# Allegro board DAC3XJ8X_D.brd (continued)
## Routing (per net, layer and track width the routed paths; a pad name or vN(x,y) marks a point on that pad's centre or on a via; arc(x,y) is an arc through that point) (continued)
ALARM: length 15.5
  BOTTOM w0.102: TP24.1 129.41,90.55 126.64,93.32 123.52,93.32 123.11,92.91 119.27,92.91 118.79,92.43 117.98,92.43 117.79,92.63 v2(116.42,92.63)
AMUX0: length 40.3
  TOP w0.152: TP2.1 133.1,74.17 v1(133.1,84.2)
  BOTTOM w0.102: v1(133.1,84.2) 134.34,84.2 135.38,85.24 135.38,86.46 134.52,87.33 133.3,87.33 132.44,86.46 132.44,85.95 130.81,84.33 128.14,84.33 126.82,85.66 125.86,85.66 124.94,84.73 118.04,84.73 118.04,84.74 117.96,84.74 117.58,85.12 117.58,85.2 116.24,86.54 115.9,86.54 115.19,87.25 114.86,87.25 114.44,87.67 114.44,87.95 114.15,88.24 114.15,88.5 v2(114.02,88.63)
AMUX1: length 27.7
  TOP w0.102: v1(125.98,84.96) 125.98,78.87 TP1.1
  BOTTOM w0.102: v1(125.98,84.96) 125.53,84.51 115.82,84.51 115.44,84.12 112.47,84.12 112.01,84.58 112.01,88.27 111.65,88.63 v2(111.62,88.63)
AN_OUT: length 2.4
  TOP w0.483: R14.1 T2.4
ANOUT: length 8.4
  TOP w0.483: J4.1 64.02,138.85 69.46,133.41 69.46,133.02 R14.2
AP_OUT: length 2.2
  TOP w0.483: T2.6 R15.2
APOUT: length 8.7
  TOP w0.483: J2.1 60.09,124.1 60.54,124.1 R2.1
ATEST: length 14.5
  TOP w0.102: v1(119.38,93.6) 118.88,93.6 118.6,93.32 117.65,93.32 117.38,93.05 116.26,93.05 115.88,93.43 U2.K9
  BOTTOM w0.102: v1(119.38,93.6) 119.66,93.88 129.01,93.88 TP23.1
BN_OUT: length 2.2
  TOP w0.483: T4.6 R27.1
BNOUT: length 8.7
  TOP w0.483: J8.1 92.07,142.08 92.39,141.76 R27.2
BP_OUT: length 2.4
  TOP w0.483: R19.2 T4.4
BPOUT: length 8.4
  TOP w0.483: R17.2 105,141.76 105.28,142.04 J6.1
CAR_SYSREFM: length 124.9
  TOP w0.229: v1(115.09,54.2) 115.09,53.78 114.65,53.34 107,53.34 106.21,54.13 106.21,64.23 105.41,65.02 102.77,65.02 100.61,67.18 93.98,67.18 R108.2
  BOTTOM w0.229: J16.G10 159.38,15.75 159.38,7.78 159.13,7.52 140.69,7.52 140.33,7.87 140.33,22 134.42,27.91 134.42,32.54 134.87,32.99 134.87,33.99 134.42,34.45 134.42,34.88 134.87,35.34 134.87,36.04 134.42,36.5 134.42,37.01 133.97,37.46 133.46,37.46 133.24,37.69 133.24,38.07 133.46,38.3 133.97,38.3 134.42,38.75 134.42,40.34 119.89,54.86 115.75,54.86 v1(115.09,54.2)
CAR_SYSREFP: length 124.9
  TOP w0.229: v1(115.78,53.51) 115.36,53.51 114.81,52.96 106.84,52.96 105.83,53.98 105.83,64.07 105.25,64.64 102.62,64.64 100.46,66.8 93.98,66.8 R109.2
  BOTTOM w0.229: v1(115.78,53.51) 116.76,54.48 119.73,54.48 134.04,40.18 134.04,38.91 133.81,38.68 133.31,38.68 132.85,38.22 132.85,37.53 133.31,37.08 133.81,37.08 134.04,36.85 134.04,27.76 139.06,22.73 139.06,8.61 140.53,7.14 159.28,7.14 160.66,8.51 160.66,15.75 J16.G9
CLK_IN: length 5.8
  TOP w0.483: C122.1 v1(82.42,49.78)
  BOTTOM w0.483: R177.2 v1(82.42,49.78)
CLK_LAO_0M: length 124.9
  BOTTOM w0.229: J16.G7 164.47,15.75 164.47,7.45 163.27,6.25 135.03,6.25 133.98,7.29 133.98,21.09 130.33,24.75 130.33,40.29 120.25,50.37 119.2,50.37 118.77,50.8 117.57,50.8 117.13,50.37 116.65,50.37 116.3,50.72 115.81,50.72 115.46,50.37 114.98,50.37 114.62,50.72 114.14,50.72 113.78,50.37 113.04,50.37 112.81,50.6 112.81,51.29 112.36,51.74 111.66,51.74 111.21,51.29 111.21,50.6 110.98,50.37 110.6,50.37 110.37,50.6 110.37,51.24 109.92,51.69 109.22,51.69 108.77,51.24 108.77,50.6 108.54,50.37 107.65,50.37 106.17,51.85 106.17,57.35 104.85,58.67 96.65,58.67 v1(96.27,59.06)
CLK_LAO_0P: length 124.9
  BOTTOM w0.229: v1(96.27,57.91) 96.65,58.29 104.69,58.29 105.79,57.2 105.79,51.69 107.49,49.99 108.7,49.99 109.15,50.44 109.15,51.08 109.38,51.31 109.76,51.31 109.99,51.08 109.99,50.44 110.44,49.99 111.14,49.99 111.59,50.44 111.59,51.13 111.82,51.36 112.2,51.36 112.43,51.13 112.43,50.44 112.88,49.99 120.09,49.99 129.95,40.13 129.95,24.59 132.72,21.82 132.72,8.02 134.87,5.87 163.42,5.87 165.68,8.13 165.68,15.8 J16.G6
CLKIN: length 5.1
  BOTTOM w0.483: R177.1 J17.1
CLKIN1N: length 3.9
  TOP w0.229: U5.35 83.35,53.6 83.29,53.54 83.29,52.34 C78.2 C198.2
CLKIN1P: length 2.8
  TOP w0.229: C122.2 82.91,52.43 82.91,53.54 82.85,53.6 U5.34
CLKLA_0N: length 8.8
  TOP w0.229: U5.63 91.56,62.31 91.62,62.25 92.6,62.25 93.34,61.5 93.34,59.09 93.76,58.67 94.87,58.67 C89.2 R80.1
CLKLA_0P: length 8.8
  TOP w0.229: R79.1 C86.2 94.87,58.29 93.6,58.29 92.96,58.93 92.96,61.34 92.44,61.87 91.62,61.87 91.56,61.81 U5.62
CLKN: length 20.1
  TOP w0.229: 83.69,86.36 83.31,85.98 83.31,79.5 81.28,77.47 80.55,77.47 78.82,75.74 78.82,74.12 80.75,72.19 80.75,71.09 R182.1 81.18,70.66 81.18,69.75 C340.2
CLKOUT0_N: length 1.6
  TOP w0.483: J18.1 C83.2
CLKOUT0_P: length 1.6
  TOP w0.483: J13.1 C79.2
CLKOUT1_N: length 2
  TOP w0.483: J20.1 C93.2
CLKOUT1_P: length 2
  TOP w0.483: J19.1 C91.2
CLKP: length 20.1
  TOP w0.229: 82.55,86.36 82.93,85.98 82.93,79.66 81.12,77.85 80.39,77.85 78.44,75.9 78.44,73.96 80.37,72.03 80.37,71.17 R181.1 79.88,70.69 C341.2
CMOS_SYNC_AB: length 113.1
  TOP w0.152: v1(149.99,34.93) 149.99,22.23 149.22,21.46 149.22,15.14 148.77,14.68 147.75,14.68 v2(147.32,15.11) ; v1(122.55,90.81) 122.63,90.73 122.63,81.2 v1(122.33,80.9) ; J21.1 144.65,82.02 144.65,80.3 145.58,79.38 147.22,79.38 147.45,79.15 v1(147.45,59.31)
  BOTTOM w0.152: v1(147.45,59.31) 147.45,40.01 149.99,37.47 v1(149.99,34.93) ; v2(116.42,91.03) 116.59,91.2 118.08,91.2 118.18,91.3 119.79,91.3 119.85,91.24 121.23,91.24 121.62,90.86 122.1,90.86 122.15,90.81 v1(122.55,90.81) ; v1(122.33,80.9) 122.63,81.2 122.73,81.2 123.19,81.66 138.94,81.66 140.72,83.44 143.23,83.44 J21.1
CMOS_SYNC_CD: length 106.5
  TOP w0.152: v1(149.1,36.32) 149.1,23.88 148.08,22.86 148.08,15.62 v2(148.59,15.11) ; v1(123.31,80.9) 123.31,88.64 123.05,88.9 123.05,91.3 v1(123.06,91.31) ; J21.3 144.78,79.35 v1(144.78,59.31)
  BOTTOM w0.152: v1(123.31,80.9) 124.08,80.14 129.16,80.14 129.64,80.62 J21.3 ; v1(144.78,59.31) 144.78,40.64 v1(149.1,36.32) ; v1(123.06,91.31) 122.73,91.31 122.36,91.68 116.98,91.68 116.84,91.83 v2(116.42,91.83)
CN_OUT: length 2.4
  TOP w0.483: T6.4 R41.2
CNOUT: length 8.4
  TOP w0.483: R42.2 133.32,141.76 133.6,142.04 J10.1
CP1: length 56.5
  TOP w0.152: U5.32 81.53,54.72 81.58,54.66 81.58,54.3 81.53,54.25 81.53,53.58 81.58,53.52 81.58,53.16 81.53,53.1 81.53,52.7 v1(80.01,51.18) C61.1 ; C120.2 115.54,37.62 v1(114.93,38.23) 111.44,38.23 Y1.1
  BOTTOM w0.152: v1(80.01,51.18) 80.52,50.67 82.93,50.67 83.31,50.29 84.84,50.29 85.34,49.78 86.36,49.78 87.63,48.51 87.63,40.01 88.77,38.86 114.3,38.86 v1(114.93,38.23)
CP2: length 3.7
  TOP w0.152: U5.46 88.86,52.11 C63.1 C62.1
CP_OUT: length 2.2
  TOP w0.483: T6.6 R102.2
CPLD_SYNC: length 67
  TOP w0.305: U1.82 v1(45.95,81.25)
  BOTTOM w0.483: SJP2.3 97.28,66.33 97.18,66.42 93.22,66.42 92.57,65.77 92.2,65.4 92.07,65.28 91.71,64.91 88.48,64.91 88.12,65.28 87.99,65.41 87.88,65.41 86.61,66.68 78.51,66.68 78.14,67.04 62.25,67.04 60.45,68.83 60.45,78.23 58.8,79.88 46.58,79.88 45.95,80.52 v1(45.95,81.25)
CPOUT: length 8.7
  TOP w0.483: J9.1 120.4,142.08 120.71,141.76 R30.2
DAC_RESET: length 134.4
  TOP w0.102: U1.37 49.45,99.73 49.28,99.9 v1(49.28,103.25)
  TOP w0.152: R63.2 SW1.3 SW1.4 C168.1
  BOTTOM w0.102: v1(142.24,90.04) 138.43,90.04 137.34,91.14 132.59,91.14 131.7,90.25 131.7,88.39 131.47,88.16 128.5,88.16 127.76,88.9 127.76,91.74 126.42,93.09 123.85,93.09 123.44,92.68 119.37,92.68 118.88,92.2 116.59,92.2 116.58,92.21 116.26,92.21 116.26,92.2 115.95,92.2 115.62,92.53 v2(115.62,92.63) 116.03,93.04 116.66,93.04 117.22,93.6 117.22,94.23 117.73,94.73 117.73,96.65 119.13,98.04 119.13,104.67 117.63,106.17 97.54,106.17 96.39,105.03 52.7,105.03 50.93,103.25 v1(49.28,103.25)
DAC_SCLK: length 86.1
  TOP w0.102: U1.33 51.45,102.96 v1(52.04,103.56)
  BOTTOM w0.102: v2(116.42,93.43) 116.81,93.82 116.81,96.37 118.87,98.43 118.87,104.27 117.22,105.92 97.79,105.92 96.65,104.78 76.66,104.78
  BOTTOM w0.152: 76.66,104.78 53.26,104.78 v1(52.04,103.56)
DAC_SDENB: length 96.6
  TOP w0.102: U2.M9 117.52,93.73 v1(117.98,93.73)
  TOP w0.152: v1(50.95,104.32) U1.34
  BOTTOM w0.102: 54.1,105.28 96.16,105.28 97.31,106.43 117.98,106.43 119.38,105.03 119.38,97.66 118.57,96.85 118.57,95.71 118.82,95.45 119.94,95.45 120.07,95.58 122.2,95.58 122.61,95.18 122.61,94.82 122.05,94.26 118.93,94.26 118.4,93.73 v1(117.98,93.73)
  BOTTOM w0.152: v1(50.95,104.32) 51.36,104.32 52.45,105.41 53.98,105.41 54.1,105.28
DAC_SDIO: length 99
  TOP w0.102: v1(118.24,95.25) 118.24,94.84 118.01,94.62 116.84,94.62 116.45,94.23 U2.L10 ; v1(121.41,95.12) v1(122.43,98.55)
  TOP w0.152: U1.35 v1(50.45,107.06)
  BOTTOM w0.102: v1(121.41,95.12) 118.36,95.12 v1(118.24,95.25) ; v1(122.43,98.55) 121.67,98.55 120.9,99.31 120.9,106.43 119.38,107.95 96.11,107.95 94.97,106.81 55.75,106.81 55.37,107.19 50.57,107.19 v1(50.45,107.06)
DAC_SDO: length 102.9
  TOP w0.102: v2(122.17,95) 122.18,95 v1(122.68,97.66) ; v2(118.36,94.23) 117.92,94.23 117.9,94.21 117.56,94.21 117.54,94.23 U2.M10
  TOP w0.152: U1.36 v1(49.95,107.57)
  BOTTOM w0.102: v1(122.68,97.66) 123.57,97.66 123.82,97.92 123.82,99.31 122.3,100.84 121.16,100.84 121.16,106.68 119.63,108.2 95.91,108.2 94.77,107.06 87.05,107.06 86.08,108.03 83.16,108.03 82.5,107.37 81.36,107.37 80.99,107.73 79.79,107.73 79.12,107.06 56.01,107.06 55.5,107.57 v1(49.95,107.57) ; v2(122.17,95) 121.77,94.59 118.73,94.59 v2(118.36,94.23)
DAC_TCLK: length 100.1
  TOP w0.102: v2(119.38,96.77) 120.32,95.83 120.32,92.23 119.53,91.44 117.02,91.44 116.81,91.24 116.81,90.02 116.64,89.84 116.03,89.84 U2.K4
  TOP w0.152: U1.40 v1(47.95,104.68)
  BOTTOM w0.102: 54.23,105.79 54.48,105.54 96.01,105.54 97.15,106.68 118.24,106.68 119.61,105.31 119.61,97 v2(119.38,96.77)
  BOTTOM w0.152: 54.23,105.79 52.02,105.79 51.64,105.41 48.64,105.41 47.95,104.72 v1(47.95,104.68)
DAC_TDI: length 100.2
  TOP w0.102: U2.L5 116.03,90.62 116.03,92.02 116.23,92.23 118.95,92.23 119.94,93.22 119.94,95.35 v1(119.38,95.91)
  TOP w0.152: U1.41 v1(47.45,105.16)
  BOTTOM w0.102: v1(47.45,105.16) 47.95,105.66 51.44,105.66 51.94,106.17 54.36,106.17 54.74,105.79 95.76,105.79 96.9,106.93 118.36,106.93 119.89,105.41 119.89,96.42 v1(119.38,95.91)
DAC_TDO: length 117
  TOP w0.102: v1(126.75,97.28) 127.38,96.65 127.38,89.53 127,89.15 v1(126.75,89.15) ; v2(121.92,89.51) 121.74,89.33 119.18,89.33 118.73,89.78 117.61,89.78 117.22,90.17 U2.M5
  TOP w0.152: U1.42 v1(46.95,105.61)
  BOTTOM w0.102: v1(46.95,105.61) 47.26,105.61 47.69,106.05 51.31,106.05 51.69,106.43 54.48,106.43 54.86,106.05 95.61,106.05 96.75,107.19 118.62,107.19 120.14,105.66 120.14,97.66 121.54,96.27 125.49,96.27 126.06,96.84 126.06,96.85 126.36,97.16 126.62,97.16 v1(126.75,97.28) ; v1(126.75,89.15) 126.44,89.15 126.16,89.43 125.84,89.43 125.79,89.48 125.41,89.48 125.36,89.43 122.28,89.43 122.23,89.48 122,89.48 121.97,89.51 v2(121.92,89.51)
DAC_TMS: length 116.9
  TOP w0.102: v1(125.6,97.03) 125.78,96.85 125.78,96.09 126.67,95.2 126.67,91.74 126.06,91.14 125.81,91.14 125.35,90.68 125.35,89.53 125.6,89.28 v1(125.6,89.03) ; v2(116.15,89.18) 116.4,89.43 U2.L4
  TOP w0.152: U1.43 v1(46.45,106.08)
  BOTTOM w0.102: v2(116.15,89.18) 116.33,89.01 116.58,89.01 116.66,88.93 120.14,88.93 120.22,88.85 120.58,88.85 120.65,88.93 125.37,88.93 125.48,89.03 v1(125.6,89.03) ; v1(125.6,97.03) 125.09,96.52 121.61,96.52 120.4,97.73 120.4,105.92 118.87,107.44 96.6,107.44 95.45,106.3 55.12,106.3 54.74,106.68 51.44,106.68 51.05,106.3 46.66,106.3 v1(46.45,106.08)
DAC_TRSTB: length 122.1
  TOP w0.102: v1(126.11,88.27) 126.11,88.9 126.31,89.1 126.31,89.33 126.57,89.59 126.8,89.59 127.13,89.92 127.13,91.42 127,91.55 127,95.76 126.11,96.65 v1(126.11,97.79) ; U2.J3 114.82,88.61 v2(114.58,88.37)
  TOP w0.152: v1(45.95,106.57) U1.44
  BOTTOM w0.102: v1(126.11,97.79) 125.72,97.79 124.7,96.77 121.69,96.77 120.65,97.82 120.65,106.17 119.13,107.7 96.27,107.7 95.12,106.55 55.5,106.55 55.12,106.93 51.05,106.93 50.69,106.57 v1(45.95,106.57) ; v2(114.58,88.37) 114.58,88.39 114.94,88.75 115.21,88.75 115.65,88.75 116.15,88.25 116.58,88.25 116.6,88.27 v1(126.11,88.27)
DCLK_N: length 30.2
  TOP w0.229: v1(105.54,92.96) 105.54,93.13 105.99,93.59 107.85,93.59 108,93.43 U2.A9
  BOTTOM w0.229: v1(83.69,87.38) 83.31,87.38 83.11,87.58 83.11,87.73 82.93,87.91 82.93,88.77 83.51,89.36 83.67,89.36 84.67,90.36 84.67,90.51 87.79,93.64 104.86,93.64 v1(105.54,92.96)
DCLK_P: length 30.2
  TOP w0.229: v1(105.54,94.62) 105.54,94.53 106.1,93.97 107.74,93.97 108,94.23 U2.A10
  BOTTOM w0.229: v1(105.54,94.62) 104.94,94.02 87.64,94.02 82.55,88.93 v1(82.55,87.38)
DCLKOUT0N: length 21.1
  TOP w0.229: U5.28 80.65,57.3 80.59,57.36 64.48,57.36 63.75,56.64 R76.1 C83.1
DCLKOUT0P: length 21.1
  TOP w0.229: C79.1 R75.1 63.75,58.47 64.48,57.74 80.59,57.74 80.65,57.8 U5.27
DCLKOUT2N: length 6.1
  TOP w0.229: C340.1 81.03,68.58 R179.1 81.03,67.17 80.77,66.91 80.77,66.45 82.85,64.37 U5.15
DCLKOUT2P: length 6.1
  TOP w0.229: U5.16 82.35,64.33 80.39,66.29 80.39,66.68 80.01,67.06 R180.1 80.01,68.58 C341.1
DCLKOUT8N: length 13
  TOP w0.229: R122.1 C74.1 97.66,53.09 96.99,53.09 96.48,53.59 95.53,53.59 95.03,53.09 94.65,53.09 94.23,53.5 94.23,56.77 93.66,57.34 92.65,57.34 92.05,56.74 91.62,56.74 91.56,56.8 U5.52
DCLKOUT8P: length 13
  TOP w0.229: U5.51 91.56,56.3 91.62,56.36 92.21,56.36 92.8,56.96 93.5,56.96 93.85,56.61 93.85,53.34 94.49,52.71 95.18,52.71 95.69,53.21 96.32,53.21 96.83,52.71 97.66,52.71 C75.1 R123.1
DN_OUT: length 2.2
  TOP w0.483: R103.2 158.92,130.37 T8.6
DNOUT: length 8.7
  TOP w0.483: R50.2 156.25,133.04 156.25,133.49 J11.1
DP0_C2M_N_A: length 100.5
  TOP w0.229: C190.1 120.6,88.01 121.13,88.01 121.23,87.91 121.23,82.5 120.03,81.3 120.03,79.04 120.01,79.02 120.01,78.71 147.9,50.82 147.9,50.39 148.28,50.02 148.7,50.02 149.66,49.06 149.66,48.51 150.15,48.02 150.7,48.02 151.18,47.54 151.18,46.99 151.67,46.5 152.22,46.5 164.08,34.64 164.08,16.69 164.92,15.85 165.73,15.85 166.73,14.86 167.64,14.86 168.28,14.22 168.66,14.22 169.04,13.84 169.04,11.43 v2(168.91,11.3)
DP0_C2M_P_A: length 100.5
  TOP w0.229: v2(170.18,11.3) 169.42,12.07 169.42,14 168.81,14.61 168.43,14.61 167.8,15.24 166.88,15.24 165.89,16.23 165.08,16.23 164.47,16.85 164.47,34.8 120.41,78.85 120.41,81.14 121.61,82.34 121.61,88.07 121.29,88.39 120.68,88.39 C191.1
DP1_C2M_N_A: length 93.5
  TOP w0.229: C193.1 117.22,83.57 116.97,83.31 116.97,79.28 122.59,73.66 122.59,73.63 135.76,60.45 135.76,25.68 141.1,20.35 141.1,19.23 141.33,19 141.33,18.49 141.1,18.26 141.1,14.64 144.3,11.43 145.06,11.43 146.94,9.56 146.94,8.26 146.05,7.37 144.72,7.37 144.27,7.82 144.27,8.38 143.89,8.76 v2(143.51,8.76)
DP1_C2M_P_A: length 93.5
  TOP w0.229: C192.1 116.46,83.57 116.59,83.44 116.59,79.12 122.21,73.5 122.21,73.47 135.38,60.29 135.38,39.19 134.87,38.68 134.87,38.3 135.38,37.79 135.38,37.41 134.87,36.9 134.87,36.52 135.38,36.01 135.38,35.63 134.87,35.12 134.87,34.74 135.38,34.23 135.38,32.71 135.05,32.38 135.05,30.94 135.38,30.61 135.38,25.53 136.38,24.53 136.38,24.25 136.86,23.76 137.15,23.76 137.35,23.56 137.35,23.28 137.83,22.79 138.12,22.79 138.32,22.59 138.32,22.31 138.8,21.82 139.09,21.82 140.72,20.19 140.72,14.48 144.14,11.05 144.91,11.05 146.56,9.4 146.56,8.41 145.89,7.75 144.88,7.75 144.72,7.91 144.72,8.7 v2(144.78,8.76)
DP2_C2M_N_A: length 86.7
  TOP w0.229: v1(138.43,8.76) 138.53,8.76 138.81,9.04 138.81,12.57 136.78,14.61 136.78,16.89 136.02,17.65 135.64,17.65 134.37,18.92 133.35,18.92 131.95,20.32 131.95,26.57 132.72,27.34 132.72,59.94 115.13,77.53 115.13,83.32 114.93,83.51 C195.1
DP2_C2M_P_A: length 86.7
  TOP w0.229: v1(139.7,8.76) 139.19,9.27 139.19,12.73 137.16,14.76 137.16,17.05 136.17,18.03 135.79,18.03 134.52,19.3 133.51,19.3 132.33,20.48 132.33,26.42 133.1,27.18 133.1,60.1 115.51,77.69 115.51,83.32 115.7,83.51 C194.1
DP3_C2M_N_A: length 90.5
  TOP w0.229: C197.1 114.04,83.89 114.02,83.89 113.79,83.66 113.79,76.36 130.3,59.85 130.3,33.76 130.61,33.45 130.61,33.02 130.3,32.72 130.3,17.18 134.52,12.95 135.69,12.95 136.91,11.73 136.91,8.54 136.05,7.68 134.15,7.68 133.73,8.1 133.73,8.26 133.35,8.64 v1(133.35,8.76)
DP3_C2M_P_A: length 90.5
  TOP w0.229: C196.1 113.41,83.77 113.41,76.2 129.92,59.69 129.92,51.64 129.69,51.41 129.69,51.03 129.92,50.8 129.92,42.93 129.36,42.37 129.36,41.46 129.92,40.9 129.92,40.52 129.41,40.01 129.41,39.63 129.92,39.12 129.92,38.74 129.41,38.24 129.41,37.85 129.92,37.35 129.92,36.97 129.41,36.46 129.41,36.08 129.92,35.57 129.92,29.95 129.72,29.75 129.72,29.06 129.92,28.86 129.92,28.58 129.72,28.38 129.72,27.69 129.92,27.49 129.92,17.02 134.37,12.57 135.53,12.57 136.53,11.58 136.53,8.7 135.89,8.06 134.81,8.06 134.62,8.26 v1(134.62,8.76)
DP4_C2M_N_A: length 90.2
  TOP w0.229: v1(128.27,8.76) 128.27,8.64 128.65,8.26 128.65,7.59 129.37,6.87 129.96,6.87 130.56,7.46 130.56,9.59 130.31,9.83 130.31,10.5 130.31,10.81 128.43,12.7 127.76,12.7 124.84,15.62 124.84,16.35 124.28,16.91 124.28,25.98 125.73,27.43 125.73,32.47 125.25,32.95 125.25,59.54 110.55,74.23 110.55,83.32 110.74,83.51 C189.1
DP4_C2M_P_A: length 90.2
  TOP w0.229: v1(129.54,8.76) 129.46,8.69 129.16,8.69 129.03,8.56 129.03,7.75 129.51,7.27 129.83,7.27 130.18,7.62 130.18,9.43 129.93,9.67 129.93,10.66 129.63,10.95 129.02,10.95 128.54,11.44 128.54,12.05 128.27,12.32 127.6,12.32 127.19,12.73 126.94,12.73 126.69,12.73 126.2,13.22 126.2,13.47 126.2,13.72 125.72,14.21 125.47,14.21 125.21,14.21 124.73,14.69 124.73,14.94 124.73,14.94 124.73,15.19 124.46,15.46 124.46,16.2 123.9,16.75 123.9,26.14 125.35,27.59 125.35,29.23 125.22,29.36 125.22,30.35 125.35,30.48 125.35,32.31 124.87,32.79 124.87,59.38 110.17,74.07 110.17,83.32 109.98,83.51 C188.1
DP5_C2M_N_A: length 97.4
  TOP w0.229: v1(123.19,8.76) 123.44,8.51 123.44,8.01 123.18,7.75 120.01,7.75 118.36,9.4 118.36,13.11 118.59,13.34 118.59,13.97 118.36,14.2 118.36,19.52 118.74,19.9 118.74,20.28 118.36,20.66 118.36,21.04 118.74,21.43 118.74,21.81 118.36,22.19 118.36,22.57 118.74,22.95 118.74,23.33 118.36,23.71 118.36,24.09 118.74,24.47 118.74,24.85 118.36,25.24 118.36,25.62 118.74,26 118.74,26.38 118.36,26.76 118.36,27.14 118.74,27.52 118.74,27.9 118.36,28.28 118.36,35.31 121.03,37.97 121.03,57.43 116.33,62.13 116.3,62.13 106.04,72.39 106.04,78.14 103.5,80.68 103.5,87.66 103.79,87.95 105.07,87.95 C40.1
DP5_C2M_P_A: length 97.4
  TOP w0.229: v1(124.46,8.76) 123.82,8.13 123.82,7.85 123.34,7.37 119.86,7.37 117.98,9.24 117.98,35.46 120.65,38.13 120.65,57.28 116.17,61.75 116.14,61.75 105.66,72.23 105.66,77.98 103.12,80.52 103.12,87.82 103.63,88.33 105.02,88.33 C39.1
DP6_C2M_N_A: length 84.5
  TOP w0.229: v1(125.73,10.03) 125.73,10.92 122.43,14.22 122.43,14.76 122.2,14.99 121.41,14.99 120.71,15.68 120.71,34.13 122.48,35.89 122.48,44.62 123.06,45.2 123.06,51.64 122.68,52.02 122.68,52.71 123.06,53.09 123.06,53.78 122.68,54.16 122.68,54.84 123.06,55.22 123.06,58.67 120.57,61.16 119.86,61.16 108.65,72.37 108.65,83.32 108.46,83.51 C38.1
DP6_C2M_P_A: length 84.5
  TOP w0.229: v1(127,10.03) 126.49,10.54 126.34,10.54 126.11,10.77 126.11,11.08 122.81,14.38 122.81,14.6 122.81,14.92 122.36,15.37 121.57,15.37 121.09,15.84 121.09,33.97 121.48,34.36 121.81,34.36 122.29,34.84 122.29,35.17 122.86,35.74 122.86,44.46 123.44,45.05 123.44,58.83 120.73,61.54 120.01,61.54 109.03,72.53 109.03,83.32 109.22,83.51 C37.1
DP7_C2M_N_A: length 83.5
  TOP w0.229: C36.1 111.63,83.57 111.76,83.44 111.76,75.28 127.51,59.53 127.51,26.52 127.28,26.29 127.28,25.61 127.51,25.38 127.51,22.84 125.98,21.32 125.98,17.11 131.09,12.01 131.09,10.95 130.81,10.67 v1(130.81,10.03)
DP7_C2M_P_A: length 83.5
  TOP w0.229: C35.1 112.39,83.63 112.14,83.38 112.14,75.44 127.89,59.69 127.89,22.68 126.36,21.16 126.36,17.27 131.47,12.17 131.47,10.9 132.08,10.29 v1(132.08,10.03)
DP_OUT: length 2.4
  TOP w0.483: T8.4 164.19,125.1 164.2,125.1
DPOUT: length 8.4
  TOP w0.483: J12.1 165.56,124.13 165.17,124.13 R43.2
EEDATA: length 20.1
  TOP w0.203: U3.61 v1(24.93,106.39)
  TOP w0.33: U4.3 13.77,107.51 v1(13.97,107.31)
  BOTTOM w0.203: v1(13.97,107.31) 14.9,106.39 v1(24.93,106.39)
EXTIO: length 35.2
  BOTTOM w0.102: v2(112.42,94.23) 112.42,94.49 112.04,94.87 112.04,95.99 112.24,96.19 112.24,96.84 112.42,97.02 112.42,97.64 C167.1
  BOTTOM w0.254: TP14.1 89.56,98.43 92.81,101.68 108.38,101.68 C167.1
FMC_B5: length 215.5
  TOP w0.102: v2(152.4,16.38) 152.4,15.49 152.02,15.11 152.02,14.35 151.66,14 151.66,12.29 151.3,11.93 150.99,11.93 150.62,11.56 150.62,8.51 151.64,7.49 172.64,7.49 173.38,8.23 173.38,11.51 175.01,13.13 175.01,14.73
  TOP w0.152: v1(149.22,71.25) 150.75,71.25 152.5,69.49 152.5,56.15 152.53,56.12 152.53,55.88 164.85,43.56 164.85,41.66 169.16,37.34 169.16,29.08 175.01,23.24 175.01,14.73 ; U1.7 58.19,87.35 60.76,84.79 60.76,72.59 61.59,71.75 v1(64.26,71.75)
  L6_PWR w0.152: v1(64.26,71.75) 73.53,71.75 75.18,70.1 91.31,70.1 91.85,70.64 133.07,70.64 133.6,70.1 141.48,70.1 142.11,70.74 149.07,70.74 149.22,70.89 v1(149.22,71.25)
FMC_B6: length 206.7
  TOP w0.102: v1(173.81,11.23) 174.02,11.43 174.02,11.48 175.39,12.85 175.39,23.5 169.67,29.21 169.67,37.72 165.48,41.91 165.48,43.82 158.88,50.42
  TOP w0.152: 158.88,50.42 158.62,50.42 152.78,56.26 152.78,69.85 151.76,70.87 151.76,71.5 v1(150.62,72.64) ; v1(63.63,72.26) 61.82,72.26 61.59,72.49 61.59,72.52 61.04,73.08 61.04,85.14 58.33,87.85 U1.8
  L6_PWR w0.102: v1(173.81,11.23) 173.05,11.99 158.88,11.99 156.26,14.61 156.26,16.28 155.4,17.15 152.91,17.15 v2(152.4,17.65)
  L6_PWR w0.152: v1(63.63,72.26) 73.79,72.26 74.68,71.37 87.88,71.37 88.26,70.99 133.48,70.99 133.98,70.49 141.1,70.49 141.86,71.25 146.69,71.25 147.32,71.88 149.86,71.88 v1(150.62,72.64)
FMC_DACCLK_N: length 123.3
  BOTTOM w0.229: 83.69,86.36 83.69,85.91 83.31,85.53 83.31,83.47 84.23,82.55 100.87,82.55 110.27,73.15 111.13,73.15 139.62,44.66 139.62,40.51 150.95,29.18 156.7,29.18 162.75,23.13 162.75,21.02 163.19,20.57 163.19,12.19 162.94,11.94 161.92,11.94 J16.D9
FMC_DACCLK_P: length 123.3
  BOTTOM w0.229: 82.55,86.36 82.55,85.91 82.93,85.53 82.93,83.31 84.07,82.17 100.71,82.17 110.11,72.77 110.97,72.77 139.24,44.5 139.24,40.36 150.79,28.8 151.79,28.8 152.02,28.58 152.02,28.17 152.25,27.94 152.63,27.94 152.86,28.17 152.86,28.58 153.08,28.8 153.47,28.8 153.69,28.58 153.69,28.17 153.92,27.94 154.3,27.94 154.53,28.17 154.53,28.58 154.76,28.8 156.54,28.8 162.37,22.97 162.37,21.02 161.92,20.57 161.92,13.21 J16.D8
FMC_DIR_CONTROL: length 168.3
  TOP w0.102: v2(151.13,17.65) 151.26,17.65
  TOP w0.152: v1(149.61,72.9) 148.46,71.75 v1(148.46,59.44) ; U1.15 57.79,91.35 57.79,91.31 59.05,90.04 59.05,88.14 61.47,85.72 61.47,73.41 61.98,72.9 v1(64.01,72.9) ; 151.26,17.65 152.02,18.42 v1(152.02,35.18)
  L6_PWR w0.152: v1(64.01,72.9) 68.07,72.9 68.33,72.64 74.17,72.64 75.01,71.81 88.34,71.81 88.77,71.37 133.86,71.37 134.37,70.87 140.84,70.87 141.6,71.63 146.05,71.63 147.32,72.9 v1(149.61,72.9)
  BOTTOM w0.152: v1(152.02,35.18) 152.02,36.83 148.46,40.39 v1(148.46,59.44)
FMC_SCLK: length 190.9
  TOP w0.102: v2(154.94,11.3) 154.94,11.18 155.45,10.67 170.28,10.67 170.94,11.33 170.94,22.35 166.88,26.42 166.88,36.07 163.19,39.75 163.19,42.55
  TOP w0.152: U1.2 57.65,84.85 59.18,83.31 59.18,70.23 60.33,69.09 v1(63.63,69.09) ; v1(150.11,68.07) 150.11,55.63 163.19,42.55
  L6_PWR w0.152: v1(150.11,68.07) 132.21,68.07 131.57,68.71 95.25,68.71 94.23,67.69 91.57,67.69 91.06,68.2 73.66,68.2 72.77,69.09 v1(63.63,69.09)
FMC_SDIO: length 195.5
  TOP w0.102: 163.45,42.8 163.45,40.13 167.26,36.32 167.26,27.31 172.08,22.48 172.08,17.24 171.96,17.11 171.96,10.92 170.66,9.63 158.62,9.63 158.37,9.88 158.37,9.91 157.99,10.29 155.45,10.29 155.19,10.54 154.94,10.54 154.18,11.3 v2(153.67,11.3)
  TOP w0.152: v1(64.26,69.6) 60.82,69.6 59.46,70.95 59.46,83.92 58.04,85.35 U1.3 ; 163.45,42.8 150.75,55.5 v1(150.75,68.45)
  L6_PWR w0.152: v1(64.26,69.6) 72.9,69.6 73.91,68.58 91.57,68.58 92.07,68.07 93.85,68.07 94.87,69.09 131.83,69.09 132.33,68.58 150.29,68.58 150.42,68.45 v1(150.75,68.45)
FMC_SDO: length 200.1
  TOP w0.102: v2(154.94,12.57) 154.43,12.07 153.42,12.07 153.03,11.68 153.03,11.3 153.8,10.54 154.05,10.54 154.43,10.16 154.43,9.91 154.69,9.65 157.99,9.65 158.37,9.27 170.94,9.27 172.34,10.67 172.34,22.86 167.64,27.56 167.64,36.7 163.7,40.64 163.7,43.17
  TOP w0.152: v1(151.26,68.96) 151.26,55.63 152.25,54.64 152.25,54.62 163.7,43.17 ; U1.4 58.04,85.85 59.82,84.07 59.82,71.25 60.83,70.23 v1(63.63,70.23)
  L6_PWR w0.152: v1(63.63,70.23) 72.95,70.23 74.22,68.96 92.46,68.96 92.96,69.47 132.21,69.47 132.72,68.96 v1(151.26,68.96)
FMC_SEN_DAC: length 204.4
  TOP w0.102: 163.96,43.43 163.96,41.02 168.15,36.83 168.15,28.07 172.72,23.5 172.72,8.64 172.34,8.26 159,8.26 157.99,9.27 153.54,9.27 151.92,10.9 151.92,11.58 152.5,12.17 152.88,12.17 153.29,12.57 v2(153.67,12.57)
  TOP w0.152: v1(151,69.72) 151.13,69.72 151.43,69.42 151.45,69.42 151.71,69.15 151.71,69.14 151.76,69.09 151.76,55.63 163.96,43.43 ; U1.5 58.05,86.35 60.2,84.2 60.2,71.63 61.09,70.74 v1(64.26,70.74)
  L6_PWR w0.152: v1(64.26,70.74) 73.02,70.74 74.42,69.34 92.07,69.34 92.58,69.85 132.59,69.85 133.1,69.34 142.11,69.34 142.49,69.72 v1(151,69.72)
FMC_SEN_LMK: length 211.2
  TOP w0.102: v2(153.67,16.38) 153.67,16.13 152.53,14.99 152.53,13.27 151.99,12.74 151.99,12.14 151.61,11.76 151.61,10.31 151.76,10.16 151.76,8.38 152.27,7.87 172.47,7.87 173.04,8.45 173.04,24.32 171.45,25.91
  TOP w0.152: U1.6 58.06,86.85 60.48,84.43 60.48,72.13 60.48,71.89 61.12,71.25 v1(63.63,71.25) ; 171.45,25.91 171.32,25.91 168.66,28.58 168.66,36.96 164.34,41.28 164.34,43.56 152.15,55.75 152.15,69.22 151.46,69.9 151.46,69.91 151.01,70.36 v1(149.73,70.36)
  L6_PWR w0.152: v1(149.73,70.36) 142.37,70.36 141.73,69.72 133.35,69.72 132.84,70.23 92.2,70.23 91.69,69.72 74.8,69.72 73.28,71.25 v1(63.63,71.25)
FMC_SYSREF_N: length 123.3
  BOTTOM w0.229: J16.D12 158.11,13.21 158.11,21.34 157.67,21.78 157.67,24.73 155.99,26.42 154.87,26.42 154.42,25.96 154.42,24.3 154.19,24.07 153.81,24.07 153.58,24.3 153.58,25.96 153.13,26.42 152.43,26.42 151.98,25.96 151.98,23.77 151.75,23.55 151.37,23.55 151.14,23.77 151.14,25.96 150.69,26.42 150,26.42 149.54,25.96 149.54,23.77 149.32,23.55 148.93,23.55 148.71,23.77 148.71,25.96 148.25,26.42 147.51,26.42 147.28,26.64 147.28,27.05 147.05,27.28 146.67,27.28 146.44,27.05 146.44,26.64 146.21,26.42 145.83,26.42 145.6,26.64 145.6,27.05 145.38,27.28 145,27.28 144.77,27.05 144.77,26.64 144.54,26.42 140.92,26.42 137.31,30.02 137.31,41.28 107.85,70.74 96.93,70.74 95.76,71.91 95.76,77.4 96.14,77.78 96.14,78.23
FMC_SYSREF_P: length 123.3
  BOTTOM w0.229: J16.D11 158.11,11.94 157.1,11.94 156.84,12.19 156.84,21.34 157.29,21.78 157.29,24.57 155.83,26.04 155.03,26.04 154.8,25.81 154.8,24.14 154.35,23.69 153.65,23.69 153.2,24.14 153.2,25.81 152.97,26.04 152.59,26.04 152.36,25.81 152.36,23.62 151.91,23.16 151.22,23.16 150.76,23.62 150.76,25.81 150.53,26.04 150.15,26.04 149.93,25.81 149.93,23.62 149.47,23.16 148.78,23.16 148.33,23.62 148.33,25.81 148.1,26.04 140.76,26.04 136.93,29.86 136.93,41.12 107.7,70.36 96.77,70.36 95.38,71.75 95.38,77.4 95,77.78 95,78.23
FPGA_CLK1N: length 129.2
  BOTTOM w0.229: J16.K5 167.08,19.48 167.08,17.42 167.48,17.02 167.76,17.02 167.84,16.94 167.87,16.94 168.2,16.61 168.2,16.58 168.35,16.43 168.35,16.15 168.83,15.67 169.14,15.67 169.47,15.34 169.47,8.33 169.94,7.86 169.94,7.54 166.11,3.71 124.82,3.71 121.03,7.49 121.03,40.44 116.61,44.86 115.72,44.86 115.44,45.14 114.4,45.14 114.12,44.86 113.35,44.86 113.02,45.19 112.66,45.19 112.33,44.86 111.98,44.86 111.65,45.19 110.9,45.19 110.57,44.86 110.04,44.86 109.74,45.15 108.49,45.15 108.19,44.86 106.02,44.86 100.46,50.42 100.46,52.63 100.01,53.09 99.44,53.09 v1(99.06,53.47)
FPGA_CLK1P: length 129.2
  BOTTOM w0.229: J16.K4 168.22,19.61 168.22,17.49 168.62,17.09 169.09,17.09 169.47,16.71 169.47,16.3 169.95,15.82 170.41,15.82 170.74,15.49 170.74,8.18 170.32,7.76 170.32,7.38 166.27,3.33 124.66,3.33 120.65,7.34 120.65,40.28 116.45,44.48 109.88,44.48 109.58,44.77 108.64,44.77 108.35,44.48 105.86,44.48 100.08,50.26 100.08,52.48 99.85,52.71 99.44,52.71 v1(99.06,52.32)
FPGA_CLK2N: length 129.2
  BOTTOM w0.229: J16.J3 169.39,18.92 169.95,18.36 171.75,18.36 172.43,17.69 172.43,7.28 167.59,2.44 123.83,2.44 118.24,8.03 118.24,39.07 116.16,41.15 112.17,41.15 111.84,41.48 111.05,41.48 110.72,41.15 110.08,41.15 109.74,41.49 109.1,41.49 108.76,41.15 108.38,41.15 107.99,41.53 107.24,41.53 106.86,41.15 105.49,41.15 98.88,47.75 98.04,47.75 v1(97.66,48.13)
FPGA_CLK2P: length 129.2
  BOTTOM w0.229: v1(97.66,46.99) 98.04,47.37 98.72,47.37 105.33,40.77 116,40.77 117.86,38.91 117.86,7.87 123.67,2.06 167.75,2.06 172.81,7.12 172.81,18.7 171.96,19.56 170.81,19.56 J16.J2
FTDI_A5: length 17.9
  TOP w0.152: U1.70 35.25,86.85 34.22,85.82 27.21,85.82 25.93,87.1 U3.22
FTDI_A6: length 17
  TOP w0.152: U1.69 35.04,87.35 34.02,86.32 27.56,86.32 26.43,87.45 U3.23
FTDI_A7: length 16.3
  TOP w0.152: U3.24 26.93,87.45 27.56,86.82 33.81,86.82 34.84,87.85 U1.68
FTDI_DAC_SDIO_READ: length 9
  TOP w0.152: U1.54 41.22,94.87 36.58,94.87 35.33,96.11 U3.44
FTDI_DIR_CONTROL: length 9
  TOP w0.152: U3.46 36.24,97.11 37.47,95.89 41.21,95.89 U1.52
FTDI_LMK_SDIO_READ: length 9
  TOP w0.152: U3.45 32.84,96.65 35.81,96.65 37.11,95.35 U1.53
FTDI_SCLK: length 9.2
  TOP w0.152: U1.61 36.03,91.35 34.29,93.09 32.82,93.09 U3.38
FTDI_SDIO: length 8.8
  TOP w0.152: U3.39 34.53,93.61 35.31,92.84 41.24,92.84 U1.58
FTDI_SDO: length 8.8
  TOP w0.152: U3.40 32.81,94.11 35.05,94.11 35.81,93.35 U1.57
FTDI_SEN_DAC: length 8.8
  TOP w0.152: U3.41 35.31,94.61 36.07,93.85 41.24,93.85 U1.56
FTDI_SEN_LMK: length 9
  TOP w0.152: U1.55 36.46,94.35 35.18,95.63 32.82,95.63 U3.43
FTDI_TCK: length 26.1
  TOP w0.152: U1.75 36.47,84.35 35.56,83.44 23.62,83.44 21.46,85.6 21.46,90.52 U3.16
FTDI_TDI: length 22.1
  TOP w0.152: U3.17 23.37,88.68 23.37,85.72 25.27,83.82 35.05,83.82 36.08,84.85 U1.74
FTDI_TDO: length 21.1
  TOP w0.152: U1.73 35.87,85.35 34.85,84.33 25.65,84.33 23.93,86.05 U3.18
FTDI_TMS: length 20.1
  TOP w0.152: U3.19 24.43,86.57 26.16,84.84 34.65,84.84 35.67,85.85 U1.72
FTDI_TRSTB: length 18.8
  TOP w0.152: U3.21 25.43,86.71 26.8,85.34 34.45,85.34 35.46,86.35 U1.71
GTX_CLKM: length 124.9
  TOP w0.229: C68.2 98.17,63.37 101,63.37 102.23,62.13 102.23,53.26 v1(102.54,52.96)
  BOTTOM w0.229: J16.D5 167,11.94 167,7.37 164.61,4.98 130.31,4.98 127.63,7.65 127.63,20.96 127.25,21.34 127.25,37.8 118.08,46.96 116.29,46.96 115.96,47.29 115.45,47.29 115.12,46.96 114.62,46.96 114.29,47.29 113.78,47.29 113.45,46.96 112.94,46.96 112.61,47.29 112.1,47.29 111.77,46.96 111.26,46.96 110.93,47.29 110.43,47.29 110.1,46.96 109.59,46.96 109.18,47.37 108.36,47.37 107.95,46.96 107.5,46.96 102.23,52.23 102.23,52.66 v1(102.54,52.96)
GTX_CLKP: length 124.9
  TOP w0.229: v1(101.55,52.96) 101.85,53.26 101.85,61.98 100.84,62.99 98.17,62.99 C67.2
  BOTTOM w0.229: v1(101.55,52.96) 101.85,52.66 101.85,52.07 107.34,46.58 117.93,46.58 126.87,37.64 126.87,21.34 126.36,20.83 126.36,8.38 130.15,4.6 164.77,4.6 168.28,8.1 168.28,11.94 J16.D4
GTXCLKM: length 10.7
  TOP w0.229: U5.2 89.36,64.51 89.42,64.57 89.42,64.96 89.87,65.41 90.93,65.41 92.58,63.75 C68.1 R68.1
GTXCLKP: length 10.6
  TOP w0.229: R67.1 C67.1 96.01,63.37 94.37,63.37 94.09,63.09 93.22,63.09 92.94,63.37 92.43,63.37 90.77,65.03 90.03,65.03 89.8,64.8 89.8,64.57 89.86,64.51 U5.1
IFORCE: length 34.8
  TOP w0.102: TP15.1 132.08,87.66 v1(132.08,84.07)
  BOTTOM w0.102: v1(132.08,84.07) 132.05,84.05 131.78,84.05 131.43,83.69 127.94,83.69 127.36,84.28 116.54,84.28 116.15,83.9 110.92,83.9 110.36,84.46 110.36,87.63 110.4,87.67 110.4,89.88 110.05,90.23 v2(110.02,90.23)
IOUTAN: length 36
  TOP w0.229: U2.C12 110.02,96.24 109.81,96.45 109.81,97.14 109.32,97.64 107.9,97.64 107.3,98.24 R117.2 106.88,98.84 106.7,98.84 106.3,99.24 106.3,100.49 105.69,101.09 104.39,101.09 104.07,101.42 R39.1 103.52,102.4 103.07,102.4 102.8,102.67 91.03,102.67 84.58,109.12 84.58,111.17 R8.1
  TOP w0.483: R9.1 R8.1
IOUTAP: length 36
  TOP w0.229: U2.B12 109.22,96.24 109.46,96.48 109.46,96.96 109.16,97.26 108.98,97.26 108.68,96.95 108.24,96.95 107.94,97.26 107.72,97.26 107.02,97.95 R114.1 106.42,98.38 106.42,98.58 105.92,99.08 105.92,100.33 105.54,100.71 104.24,100.71 103.81,101.14 R36.1 103.28,101.14 102.8,101.62 102.8,102.13 102.64,102.29 90.88,102.29 83.97,109.2 82.39,109.2 R3.2
  TOP w0.483: R5.1 R3.2
IOUTBN: length 36
  TOP w0.229: R23.1 97.21,115.77 98.5,114.48 98.5,109.14 99.34,108.31 100.88,108.31 101.54,108.97 102.01,108.97 102.24,108.74 102.24,108.1 102.69,107.65 103.47,107.65 104.13,108.31 106,108.31 106.4,108.71 107.15,108.71 107.56,108.31 109.79,108.31 109.79,108.3 109.79,105.23 109.47,104.91 R35.1 109.85,104.01 109.85,101.4 110.26,100.99 110.74,100.99 111.03,100.7 111.03,100.28 110.9,100.14 R129.2 110.9,99.25 111.03,99.11 111.03,98 111.65,97.38 111.65,97.05 111.07,96.48 111.07,96.08 U2.D12
  TOP w0.483: R25.1 R23.1
IOUTBP: length 36
  TOP w0.229: R20.2 98.88,114.4 98.88,109.3 99.5,108.69 100.72,108.69 101.38,109.35 102.17,109.35 102.62,108.9 102.62,108.25 102.85,108.03 103.31,108.03 103.97,108.69 105.84,108.69 106.24,109.09 107.31,109.09 107.72,108.69 109.94,108.69 110.17,108.46 110.17,105.23 110.49,104.91 R34.1 110.46,104.39 110.24,104.17 110.24,101.55 110.42,101.37 110.97,101.37 111.41,100.93 111.41,100.28 111.55,100.14 R118.1 111.55,99.25 111.41,99.11 111.41,98.16 112.06,97.52 112.06,96.92 111.46,96.32 111.46,95.99 U2.E12
  TOP w0.483: R21.1 R20.2
IOUTCN: length 36
  TOP w0.229: R37.1 127.25,114.45 127.25,108.61 126.72,108.08 125.79,108.08 124.91,108.97 124.43,108.97 124.2,108.74 124.2,108.1 123.67,107.57 122.78,107.57 122.05,108.31 120.44,108.31 119.91,108.84 119.25,108.84 118.85,108.43 116.78,108.43 116.65,108.3 116.65,105.23 116.97,104.91 R31.1 116.66,104.09 116.66,102.71 114.68,100.73 114.68,100.21 114.75,100.14 R131.1 114.75,99.25 114.61,99.11 114.61,98 113.99,97.38 113.99,97.06 114.57,96.48 114.57,96.08 U2.J12
  TOP w0.483: R38.1 R37.1
IOUTCP: length 36
  TOP w0.229: R32.2 126.87,114.42 126.87,108.77 126.56,108.46 125.95,108.46 125.06,109.35 124.27,109.35 123.82,108.9 123.82,108.25 123.51,107.95 122.94,107.95 122.21,108.69 120.6,108.69 120.07,109.22 119.1,109.22 118.69,108.81 116.62,108.81 116.27,108.46 116.27,105.23 115.95,104.91 R29.1 116.2,104.14 116.2,102.79 114.25,100.84 114.25,99.97 114.1,99.82 R130.2 114.1,99.25 114.23,99.11 114.23,98.16 113.58,97.51 113.58,96.92 114.19,96.32 114.19,95.99 U2.H12
  TOP w0.483: R33.1 R32.2
IOUTDN: length 36
  TOP w0.229: U2.K12 115.62,96.24 115.83,96.45 115.83,97.14 116.33,97.64 117.74,97.64 117.93,97.82 117.93,97.99 118.78,98.84 118.96,98.84 119.36,99.24 120.21,99.24 121.8,100.83 121.8,101.28 R28.1 122.36,101.84 122.94,101.84 123.43,102.34 126.18,102.34 126.51,102.67 127.49,102.67 127.82,102.34 129.5,102.34 129.73,102.57 130.76,102.57 130.98,102.34 131.62,102.34 131.95,102.67 132.41,102.67 132.74,102.34 133.83,102.34 134.39,102.9 134.39,103.23 134.66,103.5 134.99,103.5 141.27,109.77 R48.1
  TOP w0.483: R47.1 R48.1
IOUTDP: length 36
  TOP w0.229: R45.2 143.22,108.91 142.58,108.91 142.14,109.35 141.38,109.35 133.99,101.96 130.83,101.96 130.6,102.18 129.88,102.18 129.66,101.96 127.66,101.96 127.33,102.29 126.67,102.29 126.34,101.96 123.59,101.96 123.07,101.43 R26.1 122.52,100.56 122.07,100.56 120.37,98.86 119.52,98.86 119.23,98.57 119.23,98.38 R132.2 118.38,97.53 118.17,97.53 117.9,97.26 117.7,97.26 117.4,96.95 116.97,96.95 116.66,97.26 116.48,97.26 116.19,96.96 116.19,96.48 116.42,96.24 U2.L12
  TOP w0.483: R46.1 R45.2
J1_P: length 4.9
  TOP w0.483: C12.1 78.74,87.38 77.98,86.61 J1.1
J3_N: length 4.9
  TOP w0.483: C16.1 87.63,87.38 88.14,86.87 J3.1
J5_P: length 5
  TOP w0.483: J5.1 90.42,78.61 91.06,79.25 C1.1
J7_N: length 4.8
  TOP w0.483: C8.1 99.95,79.25 100.58,78.61 J7.1
LMK_CS: length 72.2
  TOP w0.152: U5.18 v1(79.83,62.31) ; v1(44.15,62.31) 43.99,62.31 33.53,72.77 33.53,79.38 35.18,81.03 43.57,81.03 43.95,81.41 U1.78
  BOTTOM w0.152: v1(79.83,62.31) 79.4,62.74 68.39,62.74 67.5,61.85 48.85,61.85 48.39,62.31 v1(44.15,62.31)
LMK_SCK: length 73.7
  TOP w0.152: v1(43.61,61.81) 42.42,63 42.41,63 33.15,72.26 33.15,80.65 33.91,81.41 43.32,81.41 43.45,81.53 U1.77 ; U5.19 80.56,61.81 v1(80.52,61.85)
  BOTTOM w0.152: v1(80.52,61.85) 80.06,61.85 80.03,61.82 79.63,61.82 79.07,62.38 68.99,62.38 68.07,61.47 43.95,61.47 v1(43.61,61.81)
LMK_SDIO: length 74.8
  TOP w0.152: U5.20 v1(79.83,61.31) ; v1(43.15,61.31) 41.78,62.68 41.78,62.74 32.77,71.75 32.77,82.3 33.12,82.65 U1.76
  BOTTOM w0.152: v1(79.83,61.31) 79.38,61.31 79.12,61.56 79.12,61.72 78.87,61.98 69.72,61.98 68.81,61.06 43.96,61.06 43.94,61.09 43.37,61.09 v1(43.15,61.31)
LMK_SDO: length 27.7
  TOP w0.152: v1(86.99,67.69) 86.99,66.42 87.88,65.53 87.88,64.29 87.86,64.27 U5.5
  BOTTOM w0.152: v1(64.26,68.33) 64.39,68.58 86.11,68.58 v1(86.99,67.69)
LMK_SYNC: length 14.9
  TOP w0.305: v1(87.25,64.52) 87.15,64.87 87.15,64.34 87.31,64.18 87.31,64.01 87.36,63.92 U5.6
  BOTTOM w0.483: SJP2.2 96.63,64.75 93.73,61.85 90.42,61.85 89.15,63.12 88.65,63.12 v1(87.25,64.52)
LPF: length 5.7
  TOP w0.102: R133.2 106.68,95.89 107.94,94.62 108.24,94.62 108.25,94.63 108.59,94.63 108.61,94.61 109.04,94.61 109.05,94.62 109.39,94.62 109.4,94.63 109.46,94.63 109.6,94.49 109.6,93.85 110.02,93.43 U2.C9
OSCI: length 9.2
  TOP w0.254: Y2.1 15.47,101.58 16.36,102.47 C42.1 17.53,101.47 17.53,100.58 20.5,97.61 U3.2
OSCIN_N: length 10.8
  TOP w0.229: U5.44 87.86,53.86 87.74,53.75 87.74,52.46 88.11,52.08 88.11,51.37 87.74,51 87.74,48.15 89.53,46.36 90.52,46.36 C82.2
OSCIN_P: length 10.8
  TOP w0.229: C92.2 89.28,45.44 89.28,46.07 87.36,47.99 U5.43
OSCO: length 12.9
  TOP w0.254: U3.3 21.18,97.11 21.13,97.16 20.32,97.16 18.8,98.68 13.84,98.68 C55.1 12.69,101.93 Y2.3
OUT_AN: length 4.7
  TOP w0.483: T1.1 T2.3
OUT_AP: length 4.7
  TOP w0.483: T2.1 T1.3
OUT_BN: length 4.7
  TOP w0.483: T4.1 T3.3
OUT_BP: length 4.7
  TOP w0.483: T4.3 T3.1
OUT_CN: length 4.7
  TOP w0.483: T6.3 T5.1
OUT_CP: length 4.7
  TOP w0.483: T6.1 T5.3
OUT_DN: length 4.7
  TOP w0.483: T8.1 151.65,123.1
OUT_DP: length 4.7
  TOP w0.483: T8.3 T7.1
RX0N: length 2.8
  TOP w0.229: C190.2 119.66,88.04 117.85,88.04 117.64,87.83 U2.M2
RX0P: length 2.8
  TOP w0.229: U2.M3 117.64,88.63 117.85,88.42 119.63,88.42 C191.2
RX1N: length 2.7
  TOP w0.229: U2.M1 117.22,86.61 117.01,86.4 117.01,84.71 C193.2
RX1P: length 2.7
  TOP w0.229: C192.2 116.63,84.68 116.63,86.4 116.42,86.61 U2.L1
RX2N: length 2.6
  TOP w0.229: C195.2 115.03,84.6 115.03,86.4 114.82,86.61 U2.J1
RX2P: length 2.7
  TOP w0.229: U2.K1 115.62,86.61 115.41,86.4 115.41,84.79 C194.2
RX3N: length 2.7
  TOP w0.229: C197.2 113.81,84.74 113.81,86.4 114.02,86.61 U2.H1
RX3P: length 2.7
  TOP w0.229: C196.2 113.43,84.65 113.43,86.4 113.22,86.61 U2.G1
RX4N: length 2.7
  TOP w0.229: U2.D1 110.82,86.61 110.61,86.4 110.61,84.64 C189.2
RX4P: length 2.7
  TOP w0.229: U2.C1 110.02,86.61 110.23,86.4 110.23,84.75 C188.2
RX5N: length 2.8
  TOP w0.229: C40.2 106.1,88.04 107.8,88.04 108,87.83 U2.A2
RX5P: length 2.7
  TOP w0.229: C39.2 105.97,88.42 107.8,88.42 108,88.63 U2.A3
RX6N: length 2.7
  TOP w0.229: U2.A1 108.42,86.61 108.63,86.4 108.63,84.68 C38.2
RX6P: length 2.7
  TOP w0.229: C37.2 109.01,84.71 109.01,86.4 109.22,86.61 U2.B1
RX7N: length 2.7
  TOP w0.229: U2.E1 111.62,86.61 111.83,86.4 111.83,84.7 C36.2
RX7P: length 2.7
  TOP w0.229: C35.2 112.21,84.69 112.21,86.4 112.42,86.61 U2.F1
SDCLKOUT1N: length 21.1
  TOP w0.229: C93.1 R84.1 68.78,50.22 68.2,50.8 68.2,52.42 68.95,53.17 77.17,53.17 80.36,56.36 80.59,56.36 80.65,56.3 U5.30
SDCLKOUT1P: length 21.1
  TOP w0.229: C91.1 R83.1 67.11,50.22 67.82,50.93 67.82,52.58 68.79,53.55 77.01,53.55 80.2,56.74 80.59,56.74 80.65,56.8 U5.29
SDCLKOUT3N: length 6.1
  TOP w0.229: R106.1 85.04,68.4 85.04,67.74 R89.1 85.22,67.03 84.36,66.17 84.02,66.17 83.79,65.94 83.79,64.57 83.85,64.51 U5.13
SDCLKOUT3P: length 6.1
  TOP w0.229: R105.1 84.35,68.43 84.35,67.72 R98.1 84.55,67.22 84.55,66.89 84.2,66.55 83.87,66.55 83.41,66.1 83.41,64.57 83.35,64.51 U5.14
SDCLKOUT9N: length 13
  TOP w0.229: U5.50 91.72,55.8 92.58,54.94 92.58,52.61 95.35,49.84 95.35,47.98 95.58,47.75 95.81,47.75 96.19,48.13 C95.1 R125.1
SDCLKOUT9P: length 13
  TOP w0.229: R124.1 C94.1 96.19,46.99 95.81,47.37 95.43,47.37 94.97,47.82 94.97,49.68 92.2,52.45 92.2,54.78 91.68,55.3 U5.49
SLEEP: length 39.9
  TOP w0.102: JP4.2 149.48,100.2 145.54,96.27 141.22,96.27 138.56,93.6 v1(138.56,91.57) ; v1(118.49,92.84) 118.36,92.96 117.98,92.96 117.65,92.63 U2.M8
  BOTTOM w0.102: v1(138.56,91.57) 128.91,91.57 126.92,93.55 123.22,93.55 122.81,93.14 119.18,93.14 118.87,92.84 v1(118.49,92.84)
SYNC: length 2.7
  BOTTOM w0.483: SJP2.1 J22.1
SYNCN: length 132.8
  TOP w0.229: v2(158.75,15.11) 159.97,16.34 v1(159.97,31.75) ; v1(154.94,86.03) 154.64,85.72 154.25,85.72 153.67,85.14 153.67,70.49 154.31,69.85 154.31,62.71 157.99,59.02 157.99,57.45 v1(157.69,57.15)
  BOTTOM w0.229: v1(154.94,86.03) 154.64,85.72 147.88,85.72 147.63,85.98 146.71,85.98 146.46,85.72 145.55,85.72 145.29,85.98 144.38,85.98 144.12,85.72 143.21,85.72 142.95,85.98 142.04,85.98 141.79,85.72 140.94,85.72 138.26,83.05 118.42,83.05 118.28,83.18 116.57,83.18 116.43,83.05 116.32,82.93 110.24,82.93 107.7,85.47 107.7,90.93 108,91.24 108.6,91.24 108.8,91.03 v2(109.22,91.03) ; v1(159.97,31.75) 160.27,32.05 160.27,36.96 157.99,39.24 157.99,56.85 v1(157.69,57.15)
SYNCP: length 132.9
  TOP w0.229: v1(160.96,31.75) 160.73,31.53 160.58,31.53 160.35,31.3 160.35,16.18 159.89,15.72 159.89,15.24 v2(160.02,15.11) ; v1(158.67,57.15) 158.37,57.45 158.37,59.18 154.69,62.87 154.69,70.01 154.05,70.64 154.05,84.99 154.41,85.34 154.64,85.34 v1(154.94,85.04)
  BOTTOM w0.229: v1(160.96,31.75) 160.66,32.05 160.66,37.11 158.37,39.4 158.37,56.85 v1(158.67,57.15) ; v1(154.94,85.04) 154.64,85.34 141.1,85.34 138.42,82.66 118.27,82.66 118.13,82.8 116.73,82.8 116.59,82.66 116.48,82.55 110.08,82.55 107.31,85.31 107.31,91.09 107.84,91.62 108.6,91.62 108.8,91.83 v2(109.22,91.83)
SYS_N: length 30.2
  TOP w0.229: U2.A6 108,91.03 107.8,91.24 107.46,91.24 106.9,90.68 106.68,90.68 106.04,90.04 R6.2 104.9,90.68 102.42,90.68 101.86,91.24 100.51,91.24 100.03,90.75 98.07,90.75 97.59,91.24 96.47,91.24 95.76,90.52 95.76,87.57 95.99,87.34 96.07,87.34 96.57,86.84 96.57,86.17 96.07,85.67 95.22,85.67 95,85.44 95,84.98 95.22,84.75 96.07,84.75 96.55,84.27 96.55,83.55 96.07,83.08 95.22,83.08 95,82.85 95,82.39 95.12,82.26 95.12,80.24 95.47,79.89 95.91,79.89 96.14,79.66 v1(96.14,79.25)
SYS_P: length 30.2
  TOP w0.229: U2.A7 108,91.83 107.8,91.62 107.3,91.62 106.9,91.21 106.6,91.21 105.99,91.82 R10.2 105.03,91.31 105.03,91.29 104.8,91.06 102.58,91.06 102.02,91.62 100.35,91.62 99.87,91.14 98.23,91.14 97.75,91.62 96.32,91.62 95.38,90.68 95.38,87.41 95.83,86.96 95.91,86.96 96.14,86.73 96.14,86.28 95.91,86.05 95.07,86.05 94.61,85.6 94.61,84.82 95.07,84.37 95.91,84.37 96.14,84.14 96.14,83.69 95.91,83.46 95.07,83.46 94.61,83 94.61,82.23 94.74,82.1 94.74,80.08 95,79.83 v1(95,79.25)
SYSREF_M: length 10.7
  TOP w0.229: R70.1 R108.1 91.72,67.56 90.35,68.94 89.22,68.94 88.42,68.13 88.42,64.57 88.36,64.51 U5.4
SYSREF_P: length 10.6
  TOP w0.229: R69.1 92.33,65.53 92.33,66.17 R109.1 91.82,67.18 91.57,67.18 90.2,68.55 89.38,68.55 88.8,67.97 88.8,64.57 88.86,64.51 U5.3
SYSREFN: length 20.1
  TOP w0.229: R106.2 85.34,70.69 R116.2 85.22,71.33 84.9,71.65 84.9,71.88 85.28,72.26 86.2,72.26 87.73,70.74 93.09,70.74 95.76,73.41 95.76,77.85 96.14,78.23
SYSREFP: length 20.1
  TOP w0.229: R105.2 84.07,70.69 R115.2 84.2,71.33 84.52,71.65 84.52,72.04 85.13,72.64 86.36,72.64 87.88,71.12 92.93,71.12 95.38,73.56 95.38,77.85 95,78.23
TCK: length 21.6
  TOP w0.152: J15.1 59.08,112.75 59.08,96.29 58.64,95.85 U1.24
  BOTTOM w0.152: R57.1 J15.1
TDI: length 33.9
  TOP w0.152: U1.23 59.66,95.35 59.94,95.63 v1(59.94,110.11)
  BOTTOM w0.152: v1(59.94,110.11) 58.29,110.11 58.17,109.98 49.66,109.98 49.28,110.36 49.28,112.4 J15.9 R110.1
TDO: length 17.7
  TOP w0.152: J15.3 56.65,112.64 U1.25
TESTMODE: length 34.6
  TOP w0.102: v2(115.37,88.37) 115.62,88.62 U2.K3
  TOP w0.152: v1(135.76,87) 135.76,77.47 TP25.1
  BOTTOM w0.102: v1(135.76,87) 135.38,87.38 134.79,87.38 134.61,87.55 133.2,87.55 133.03,87.38 127.25,87.38 124.97,85.09 119.3,85.09 119.18,84.96 118.4,84.96 118.4,84.96 118.13,84.96 118.13,84.96 118.06,84.96 117.81,85.22 117.81,85.29 117.47,85.62 117.47,85.72 115.82,87.38 115.46,87.38 115.2,87.63 115.2,87.97 115.37,88.14 v2(115.37,88.37)
TMS: length 35.3
  TOP w0.152: v1(60.83,116.33) 60.83,95.63 60.07,94.87 60.07,94.85 U1.22
  BOTTOM w0.152: J15.5 53.09,113.79 ; 53.09,113.79 55.68,116.38 58.56,116.38 58.61,116.33 v1(60.83,116.33) ; 53.09,113.79 R111.1
TXENABLE: length 48.7
  TOP w0.102: JP1.2 153.42,101.47 148.46,101.47 146.94,99.95 134.11,99.95 132.72,98.55 124.59,98.55 123.44,97.41 123.44,95.5 121.16,93.22 v1(121.16,89.79)
  BOTTOM w0.102: v1(121.16,89.79) 118.72,89.79 118.67,89.74 118.31,89.74 118.06,89.99 118.06,90.5 117.63,90.93 116.87,90.93 116.58,90.65 116.02,90.65 115.85,90.47 115.85,90.46 v1(115.62,90.23)
USB_DM: length 9.1
  TOP w0.229: U3.7 20.17,95.11 20.11,95.05 19.5,95.05 v1(19.18,95.38)
  BOTTOM w0.229: v1(12.95,95.38) 13.36,94.97 18.77,94.97 v1(19.18,95.38)
USB_DP: length 9.1
  TOP w0.229: U3.8 20.17,94.61 20.11,94.67 19.61,94.67 v1(19.18,94.23)
  BOTTOM w0.229: v1(12.95,94.23) 13.31,94.59 18.82,94.59 v1(19.18,94.23)
USB_EECLK: length 18.9
  TOP w0.203: v1(24.26,105.28) 24.43,105.11 U3.62 ; R60.1 v1(13.46,105.28)
  TOP w0.33: R60.1 12.52,106.86 U4.2
  BOTTOM w0.203: v1(13.46,105.28) v1(24.26,105.28)
USB_EECS: length 20.8
  TOP w0.203: v1(11.18,104.52) 11.18,104.78 ; U3.63 23.93,104.34 v1(23.75,104.52)
  TOP w0.33: U4.1 11.74,105.34 11.05,104.65 R58.1
  BOTTOM w0.203: v1(23.75,104.52) v1(11.18,104.52)
USB_REF: length 2.8
  TOP w0.254: R52.1 19.56,96.52 20.47,95.61 U3.6
USB_RST: length 2.5
  TOP w0.254: U3.14 19.09,91.61 R54.2
VSENSE: length 31.2
  BOTTOM w0.102: TP16.1 132.54,84.48 132.54,83.88 132.02,83.36 118.56,83.36 118.25,83.67 110.52,83.67 109.85,84.33 109.85,86.49 109.6,86.74 109.6,87.67 109.6,87.67 109.6,89.03 110,89.43 v2(110.02,89.43)
N16791695: length 2
  TOP w0.61: U12.4 C47.1
N16791764: length 4.4
  TOP w0.508: R51.2 10.79,96.77 10.24,96.21 J14.1
N16791900: length 6.7
  TOP w0.254: C45.1 C44.1 16.54,97.28 19.56,97.28 20.23,96.61 U3.4
  vias: v1(10.54,85.85) v1(10.67,87.5) v1(10.67,84.96) v1(11.18,86.74) v1(11.18,84.2) v1(11.81,85.85) v1(12.06,87.63) v1(12.06,84.71) v1(15.11,97.28) v1(15.75,97.28) v1(16.51,97.28)
N16791904: length 10.9
  TOP w0.254: U3.9 20.32,94.11 18.8,92.58 14.83,92.58 C46.1 14.58,92.33 C48.1 FB15.2
N16792038: length 4.1
  TOP w0.508: R55.1 11.05,94.23 10.67,94.62 J14.3
N16792040: length 3.9
  TOP w0.508: R56.1 10.5,95.38 10.33,95.42 J14.2
N16792068: length 2.4
  TOP w0.254: R61.2 R54.1 16.89,91.57
N16792392: length 3.4
  TOP w0.33: R64.1 R59.2 13.8,108.16 U4.4
N16905345: length 2.2
  TOP w0.102: R62.1 R133.1 C53.1
N16905395: length 1
  TOP w0.102: R62.2 C50.1
N16906481: length 3.5
  BOTTOM w0.102: v2(113.22,94.23) 113.28,94.23 113.6,94.55 113.6,96.8 113.54,96.86 R135.1
N16906487: length 1
  BOTTOM w0.254: 113.54,99.57 R135.2
N16918679:
  vias: v1(93.73,37.59) v1(93.73,36.7) v1(94.87,37.59) v1(94.87,36.7) v1(96.01,37.47) v1(96.01,36.7) v1(97.41,37.59) v1(97.41,36.7) v1(98.3,37.34) v1(98.3,36.32) v1(99.44,37.21) v1(99.44,36.32) v1(100.58,37.47) v1(100.58,36.32) v1(101.35,36.58) v1(102.36,36.58) v1(103.25,36.58) v1(104.14,36.58) v1(105.03,36.58) v1(105.92,36.58)
N16918713: length 7.1
  TOP w0.483: 96.9,41.22 R78.2 R87.1 100.33,40.71 Y1.5
N16918734: length 7.1
  TOP w0.483: 96.9,42.74 R73.2 R74.1 100.33,43.25 Y1.4
N16918766: length 9.6
  TOP w0.254: FB17.2 91.54,34.16 91.31,34.39 JP2.1
N16918796: length 1.1
  TOP w0.483: R138.2 C80.1
N16918798: length 4.3
  TOP w0.483: C82.1 R77.1 92.69,44.19 93.79,44.19 94.15,43.83 94.15,43.11 C80.2
N16918863: length 4.3
  TOP w0.483: C206.2 93.5,41.22 R99.1 C92.1
N16918987: length 5
  TOP w0.635: Y1.2 SJP1.2
N16957588: length 5.8
  BOTTOM w0.381: U11.16 R173.2 176.66,91.19 175.89,91.19 175.51,90.81 175.51,90.17 174.98,89.64 R174.2
N16960291:
  vias: v1(19.68,48.13) v1(20.32,48.13) v1(21.59,48.01) v1(22.36,47.88) v1(23.11,47.88) v1(23.88,49.15) v1(23.88,48.01) v1(23.88,47.12) v1(24.89,48.64) v1(24.89,47.88) v1(24.89,47.12) v1(25.27,49.28) v1(25.78,48.64) v1(25.78,47.88) v1(25.78,47.12) v1(26.16,49.28) v1(26.67,48.64) v1(26.67,47.88) v1(26.67,47.12) v1(27.3,49.15) v1(27.43,48.13) v1(27.43,46.99) v1(28.19,47.12) v1(28.32,49.15) v1(28.45,48.13) v1(29.21,46.99) v1(29.46,49.15) v1(29.46,48.26) v1(30.1,46.99) v1(30.48,47.5) v1(30.61,48.39) v1(30.73,49.15) v1(31.62,49.02) v1(31.62,48.01) v1(31.62,47.12) v1(32.38,48.13) v1(32.64,49.15)
N16960299: length 5.3
  BOTTOM w0.381: Q1.3 18.53,48.62 18.73,48.82 19.11,48.82 19.14,48.83 19.19,48.88 19.22,48.88 19.23,48.89 19.43,49.02 19.57,49.02 19.63,49.08 20.06,49.08 20.18,49.09 20.39,49.3 U10.4
  BOTTOM w0.635: D9.2 U10.4
N16974113: length 51.1
  TOP w0.102: 58.67,68.45 58.83,68.3 R113.1
  TOP w0.152: 58.67,68.45 57.02,70.1 36.96,70.1 33.91,73.15 33.91,78.99 35.59,80.67 44.96,80.67 45.45,81.15 U1.81
N16976956: length 16.8
  TOP w0.152: U1.51 41.25,98.2 40.51,98.93 40.51,109.47 41.66,110.62 JP3.2
N16991585: length 6
  BOTTOM w0.305: v1(168.53,60.45) 168.9,60.83 U7.7 ; v1(168.02,60.58) 167.9,60.7 U7.9 ; U7.3 168.4,66.04 v1(168.15,66.29) 167.9,66.05 U7.2
  vias: v1(164.85,72.64) v1(165.1,74.3) v1(166.37,72.52) v1(167.89,72.52) v1(168.15,70.99) v1(168.17,69.6) v1(168.17,68.07)
N16991666: length 3
  BOTTOM w0.305: L17.1 169.4,58.44 U7.6
N16991670: length 3.7
  BOTTOM w0.305: U7.5 169.4,64.75 170.56,65.91 R148.1 R151.2
N16991672: length 7.1
  BOTTOM w0.305: C148.2 R150.1 163.32,63.12 ; 163.32,63.12 166.12,63.12 166.37,63.37 166.37,64.01 166.73,64.37 U7.1 ; 163.32,63.12 R153.2
N16992144:
  vias: v1(160.4,61.47) v1(160.4,60.33) v1(161.42,61.47) v1(161.67,60.33) v1(162.18,61.47) v1(162.81,57.02) v1(162.94,60.33) v1(162.94,59.18) v1(163.32,61.47) v1(163.32,58.17) v1(164.08,59.94) v1(164.21,61.47) v1(164.21,58.29) v1(164.21,56.9) v1(165.1,61.47) v1(165.1,60.45)
N16992172: length 11.1
  TOP w0.508: v1(169.54,66.42) 172.59,66.42 173.1,65.91 173.1,62.87 v1(171.7,61.47)
  BOTTOM w0.305: v1(169.54,66.42) 169.44,66.32 169.44,65.56 169.42,65.53 168.9,65.02 U7.4
  vias: v1(171.7,60.45) v1(171.7,58.42) v1(172.59,59.56) v1(172.97,61.47) v1(173.1,60.07) v1(173.1,58.42)
N16994752: length 3
  BOTTOM w0.305: U7.10 167.4,58.44 L18.1
N17000669: length 5.9
  BOTTOM w0.381: R176.2 175.11,75.03 175.64,75.56 175.64,76.33 175.92,76.61 R175.1 U9.16
N17014647: length 15.1
  TOP w0.254: v1(86.61,53.47) 86.86,53.71 U5.42
  TOP w0.305: v1(89.41,53.47) 89.36,53.54 U5.47
  BOTTOM w0.381: v1(90.04,49.78) 90.04,50.06 90.27,50.29 90.55,50.29 90.55,51.05 90.42,51.18 90.42,52.32 90.61,52.51 90.61,52.9 90.04,53.47 v1(89.41,53.47) 89.28,53.47 88.9,53.09 87.88,53.09 87.5,53.47
  BOTTOM w0.508: v1(86.61,53.47) 86.87,53.21 C64.1 ; v1(86.61,53.47) 87.12,53.98 FB5.1 87.25,54.86 C65.1 C66.1 ; v1(86.61,53.47) 87.5,53.47
  vias: v1(89.28,49.78) v1(89.28,48.77) v1(89.66,49.28) v1(90.04,48.77)
